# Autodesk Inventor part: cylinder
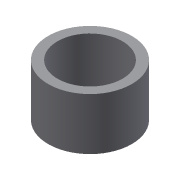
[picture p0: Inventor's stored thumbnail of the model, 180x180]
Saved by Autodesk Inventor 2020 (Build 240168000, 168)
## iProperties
Part Number: cylinder
Document SubType Name: Modeling
Created: 2003-01
Designer: Owner
Density: 1 g/cm^3
Material: Generic
Appearance: Default
Control State: 0
Master: False
Checked Out: False
Shininess: 64.0
Length Units: 11269
Angle Units: 11279
Time Units: 11290
Mass Units: 11283
Length Display Precision: 3
Angle Display Precision: 2
Compacted: True
Density: 0.0
Volumn: 0.0
Area: 0.0
PropertySet Name: Model Information
Author: Owner
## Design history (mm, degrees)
sketch "Sketch1"
  geometry: C1 r 112.5 at (0, 0); C2 r 87.5 at (0, 0)
  constraints: 2 centre point, 1 coincident, 1 concentric
  dimensions: "d0" = 225 diameter of C1; "d1" = 175 diameter of C2
extrude "Extrusion1" new body sketch "Sketch1" stored distance "d2" = 140; taper "d3" = 0 deg
body "Solid1"
